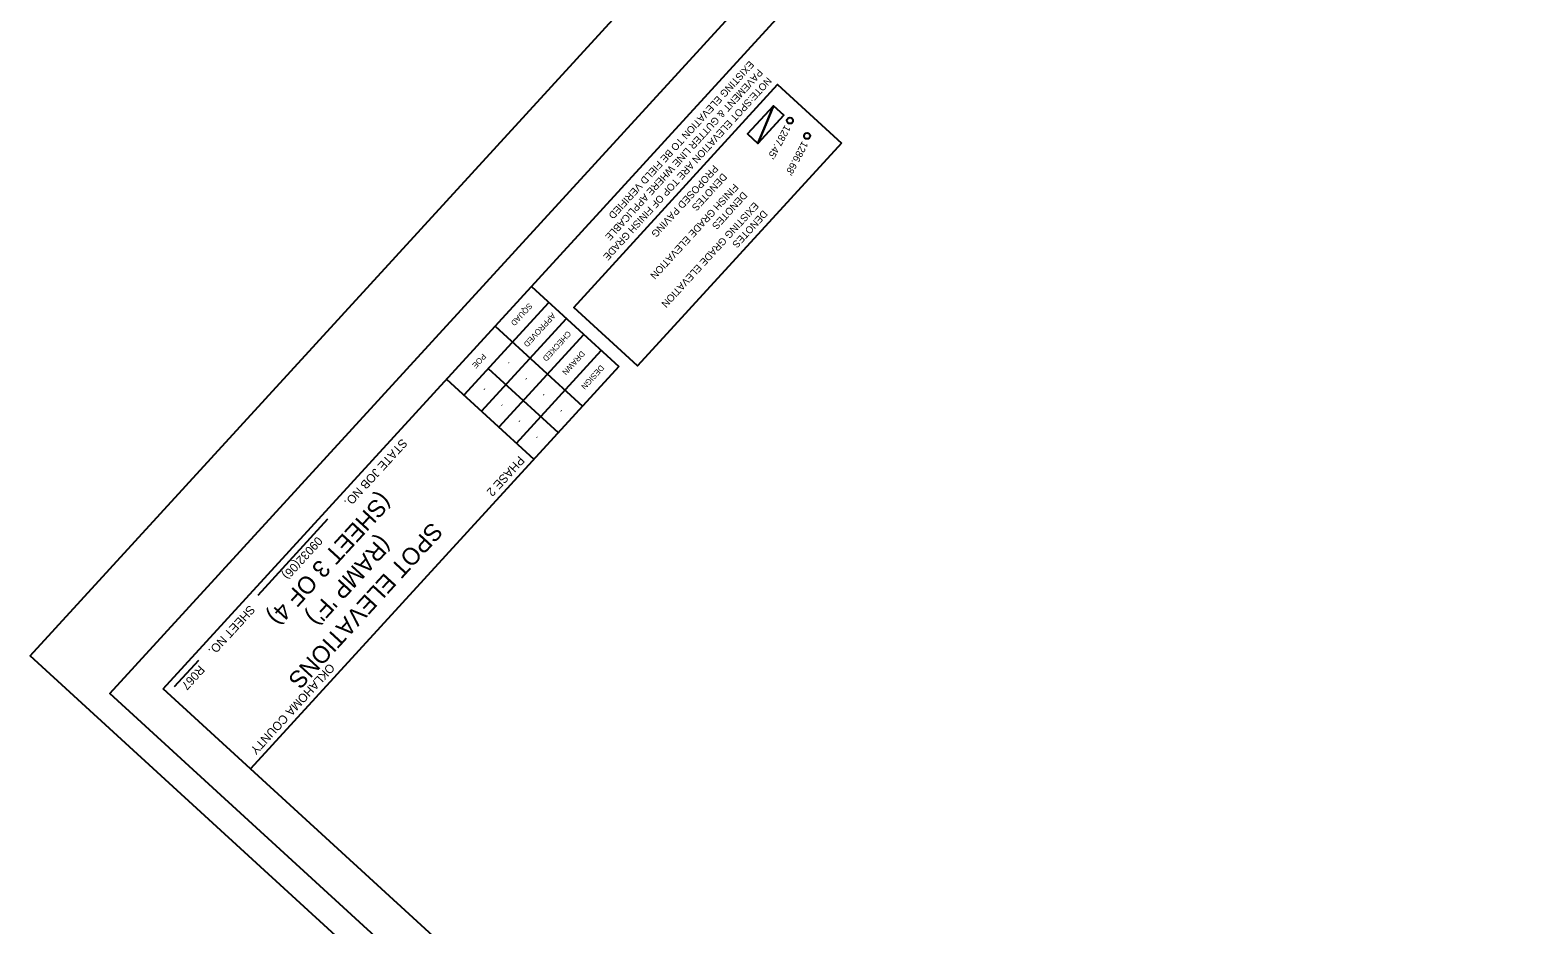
# Model space of a CAD drawing. Extents: x 2149167 to 2150427, y 142619 to 143901.
# Drawn here: x 2149167 to 2149797, y 142992 to 143366 of the extents above; entities that cross this region are included whole.
import ezdxf

# ---------------------------------------------------------------- set-up
doc = ezdxf.new("R2010")
doc.units = 0
for name, color, linetype in [('EX_Align_Text', 7, 'Continuous'), ('INR_Tracking', 7, 'Continuous'), ('PR_Improvements_Txt', 7, 'Continuous'), ('PR_Misc_Improvement', 7, 'Continuous'), ('PR_Road_Concrete', 7, 'Continuous'), ('PR_Shading_1', 7, 'Continuous'), ('SHT_Plot_Shape_Half', 7, 'Continuous'), ('SHT_Sheet_Border', 7, 'Continuous'), ('SHT_Standard_Sheet_Txt', 7, 'Continuous'), ('TOPO_Curb Gut', 7, 'Continuous'), ('TOPO_Fence', 7, 'Continuous'), ('TOPO_RR Rail', 7, 'Continuous')]:
    doc.layers.add(name, color=color, linetype=linetype)

msp = doc.modelspace()

# ---------------------------------------------------------------- linework, layer by layer
at = {"layer": 'PR_Improvements_Txt'}
for points in [[(2149505.95, 143319.11), (2149420.72, 143226.04), (2149394.09, 143250.42), (2149479.32, 143343.5)], [(2149481.89, 143330.76), (2149471.07, 143318.95), (2149466.78, 143322.88), (2149477.59, 143334.69)]]:
    msp.add_lwpolyline(points, close=True, dxfattribs=at)
at = {"layer": 'PR_Misc_Improvement'}
for centre in [(2149484.45, 143328.49), (2149491.61, 143322.08)]:
    msp.add_circle(centre, 1.27, dxfattribs=at)
at = {"layer": 'PR_Road_Concrete'}
msp.add_line((2149477.59, 143334.69), (2149471.07, 143318.95), dxfattribs=at)
at = {"layer": 'PR_Shading_1'}
msp.add_lwpolyline([(2149477.59, 143334.69), (2149474.33, 143326.82), (2149471.07, 143318.95), (2149481.89, 143330.76), (2149477.59, 143334.69)], dxfattribs=at)
at = {"layer": 'SHT_Plot_Shape_Half'}
msp.add_lwpolyline([(2150375.82, 143395.55), (2149686.97, 142643.3), (2149200.22, 143089.02), (2149889.06, 143841.28)], close=True, dxfattribs=at)
at = {"layer": 'SHT_Sheet_Border'}
for p, q in [((2149376.4, 143259.21), (2149412.91, 143225.78)), ((2149412.91, 143225.78), (2149258.93, 143057.63)), ((2149340.94, 143220.49), (2149377.47, 143187.05))]:
    msp.add_line(p, q, dxfattribs=at)
msp.add_lwpolyline([(2149222.42, 143091.06), (2149860.62, 143788), (2150325.25, 143362.54), (2149687.05, 142665.6)], close=True, dxfattribs=at)
at = {"layer": 'TOPO_Curb Gut'}
msp.add_lwpolyline([(2150427.25, 143415.07), (2149697.88, 142618.56), (2149166.87, 143104.81), (2149896.24, 143901.31)], close=True, dxfattribs=at)
at = {"layer": 'TOPO_Fence'}
for p, q in [((2149361.2, 143242.62), (2149397.73, 143209.17)), ((2149358.38, 143224.87), (2149387.6, 143198.11)), ((2149291.19, 143161.89), (2149262.01, 143130.02)), ((2149237.2, 143102.93), (2149227.02, 143091.81))]:
    msp.add_line(p, q, dxfattribs=at)
for points in [[(2149348.25, 143213.81), (2149383.7, 143252.53)], [(2149355.55, 143207.12), (2149391, 143245.84)], [(2149362.85, 143200.44), (2149398.3, 143239.15)], [(2149370.15, 143193.75), (2149405.6, 143232.47)]]:
    msp.add_lwpolyline(points, dxfattribs=at)
at = {"layer": 'TOPO_RR Rail'}
msp.add_lwpolyline([(2149471.07, 143318.95), (2149474.33, 143326.82), (2149477.59, 143334.69), (2149466.78, 143322.88), (2149471.07, 143318.95)], dxfattribs=at)

# ---------------------------------------------------------------- texts
at = {"layer": 'EX_Align_Text'}
msp.add_text("1286.68' ", height=3, rotation=242.12677, dxfattribs=at).set_placement((2149489.62, 143320.1))
at = {"layer": 'INR_Tracking'}
msp.add_text("1287.45' ", height=3, rotation=241.32612, dxfattribs=at).set_placement((2149482.35, 143326.83))
at = {"layer": 'PR_Improvements_Txt'}
for s, p in [('PAVEMENT & GUTTER LINE WHERE APPLICABLE', (2149471.23, 143350.29)), ('EXISTING ELEVATION TO BE FIELD VERIFIED', (2149467.54, 143353.68)), ('NOTE:SPOT ELEVATION ARE TOP OF FINISH GRADE', (2149474.93, 143346.91)), ('PROPOSED PAVING', (2149452.59, 143310.14)), ('DENOTES', (2149456.28, 143306.76)), ('FINISH GRADE ELEVATION', (2149461.05, 143302.4)), ('DENOTES', (2149464.74, 143299.01)), ('EXISTING GRADE ELEVATION', (2149469.51, 143294.65)), ('DENOTES', (2149473.2, 143291.27))]:
    msp.add_text(s, height=3, rotation=227.51948, dxfattribs=at).set_placement(p)
at = {"layer": 'SHT_Standard_Sheet_Txt'}
for s, height, p in [('SQUAD', 2.4, (2149375.29, 143252.44)), ('APPROVED', 2.4, (2149384.98, 143248.36)), ('CHECKED', 2.4, (2149391.48, 143240.81)), ('POE', 2.4, (2149355.97, 143231.34)), ('DRAWN', 2.4, (2149397.26, 143232.46)), ('-', 2.4, (2149366.59, 143228.31)), ('DESIGN', 2.4, (2149405.29, 143226.57)), ('-', 2.4, (2149356.46, 143217.25)), ('-', 2.4, (2149373.89, 143221.62)), ('-', 2.4, (2149363.76, 143210.56)), ('-', 2.4, (2149381.2, 143214.94)), ('-', 2.4, (2149388.51, 143208.23)), ('-', 2.4, (2149371.07, 143203.87)), ('STATE JOB NO.', 3.6, (2149322.26, 143195.82)), ('-', 2.4, (2149378.38, 143197.17)), ('PHASE 2', 3.621, (2149371.23, 143188.61)), ('(SHEET 3 OF 4)', 7.2, (2149313.38, 143173.53)), ('SPOT ELEVATIONS', 7.2, (2149334.65, 143161.14)), ('09032(06)', 3.6, (2149286.82, 143154.93)), ("(RAMP 'F')", 7.2, (2149313.23, 143155.55)), ('SHEET NO. ', 3.6, (2149258.58, 143126.27)), ('R067', 3.6, (2149237.57, 143101.14)), ('OKLAHOMA COUNTY', 3.6211, (2149291.9, 143101.98))]:
    msp.add_text(s, height=height, rotation=227.51948, dxfattribs=at).set_placement(p)

doc.saveas('drawing.dxf')
